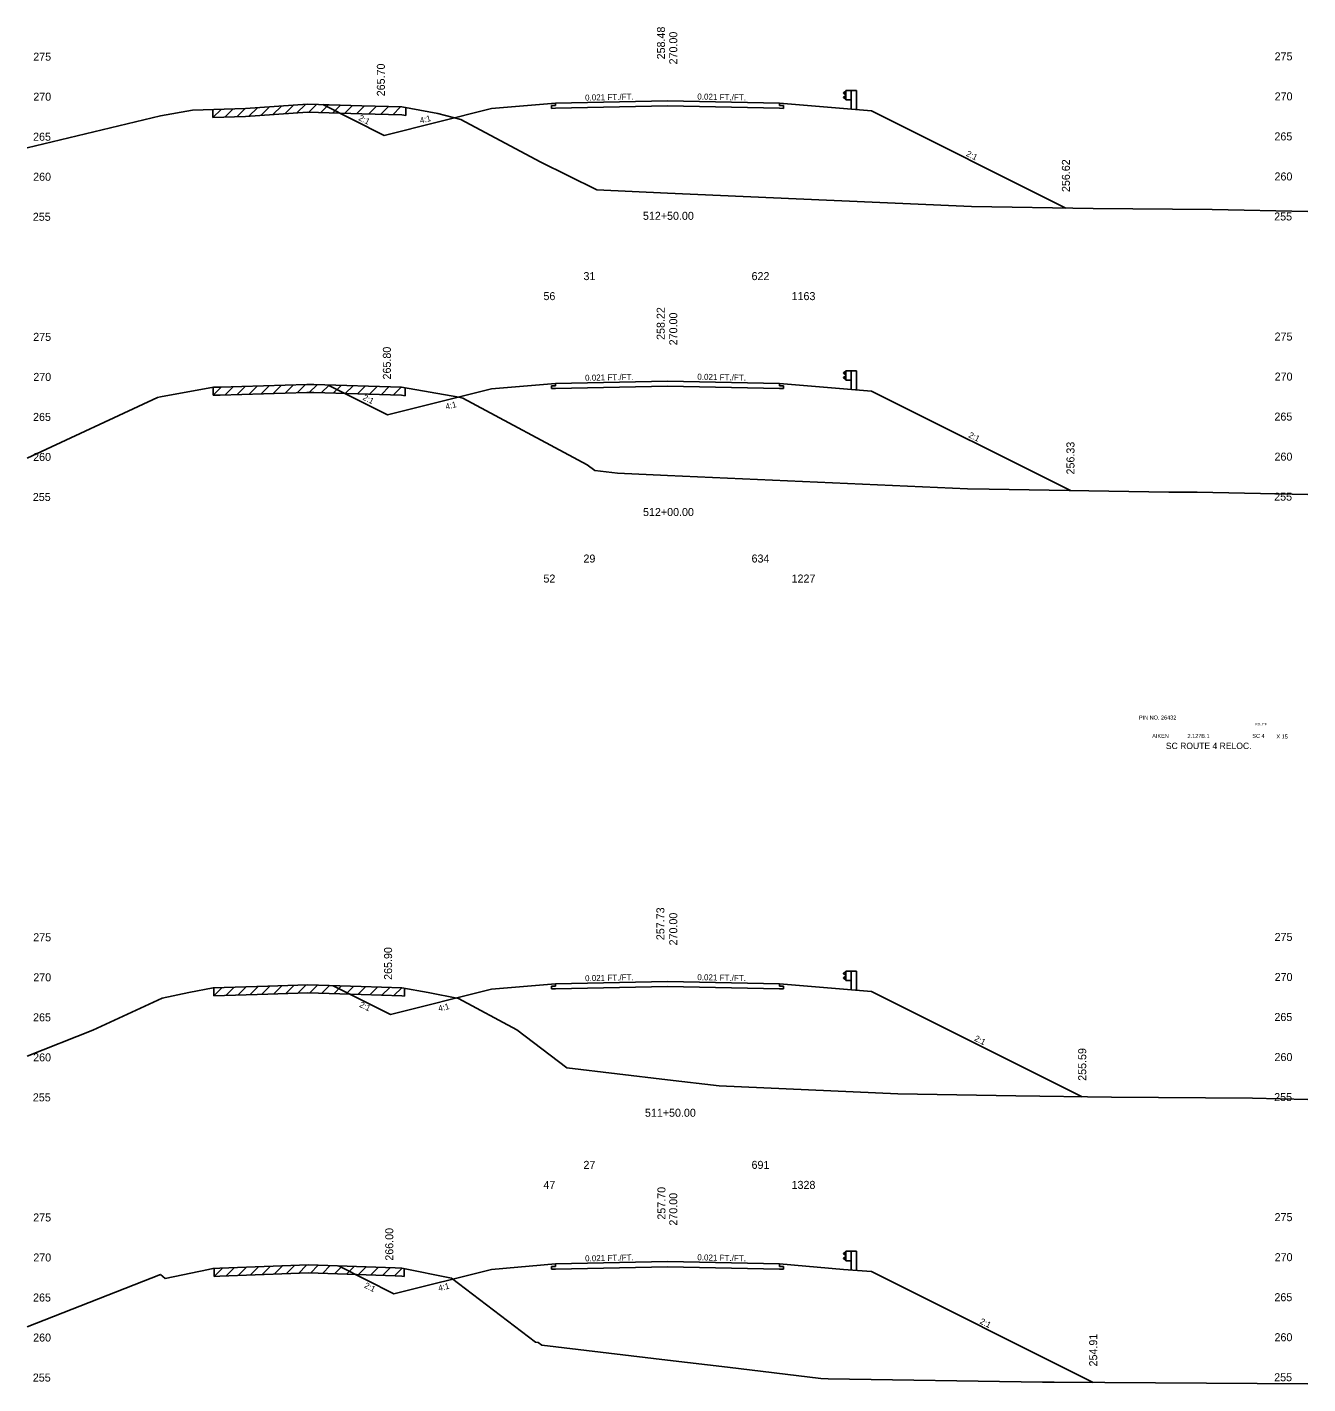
# Model space of a CAD drawing. Extents: x 2967 to 4323, y -3677 to -817.
# Drawn here: x 3188.8 to 3348.8, y -2050.1 to -1880.6 of the extents above; entities that cross this region are included whole.
import ezdxf

# ---------------------------------------------------------------- set-up
doc = ezdxf.new("R2010")
doc.units = 0
for name, color, linetype in [('Level 1', 7, 'Continuous'), ('Level 10', 7, 'Continuous'), ('Level 11', 7, 'Continuous'), ('Level 12', 7, 'Continuous'), ('Level 20', 7, 'Continuous'), ('Level 24', 7, 'Continuous'), ('Level 3', 7, 'Continuous'), ('Level 32', 7, 'Continuous'), ('Level 33', 7, 'Continuous'), ('Level 59', 7, 'Continuous'), ('Level 6', 7, 'Continuous'), ('Level 60', 7, 'Continuous'), ('Level 61', 7, 'Continuous'), ('Level 7', 7, 'Continuous')]:
    doc.layers.add(name, color=color, linetype=linetype)

msp = doc.modelspace()

# ---------------------------------------------------------------- linework, layer by layer
at = {"layer": 'Level 11'}
for p, q in [((3254.76, -1890.43), (3254.26, -1890.44)), ((3254.26, -1890.44), (3254.26, -1890.78)), ((3254.26, -1890.78), (3254.76, -1890.77)), ((3254.76, -1890.13), (3254.76, -1890.43)), ((3282.76, -1890.43), (3282.76, -1890.13)), ((3283.26, -1890.44), (3282.76, -1890.43)), ((3282.76, -1890.77), (3283.26, -1890.78)), ((3283.26, -1890.78), (3283.26, -1890.44)), ((3254.76, -1925.13), (3254.76, -1925.43)), ((3282.76, -1925.43), (3282.76, -1925.13)), ((3254.76, -1925.43), (3254.26, -1925.44)), ((3254.26, -1925.44), (3254.26, -1925.78)), ((3254.26, -1925.78), (3254.76, -1925.77)), ((3283.26, -1925.44), (3282.76, -1925.43)), ((3282.76, -1925.77), (3283.26, -1925.78)), ((3283.26, -1925.78), (3283.26, -1925.44)), ((3254.76, -2000.43), (3254.26, -2000.44)), ((3254.26, -2000.44), (3254.26, -2000.78)), ((3254.26, -2000.78), (3254.76, -2000.77)), ((3254.76, -2000.13), (3254.76, -2000.43)), ((3282.76, -2000.43), (3282.76, -2000.13)), ((3283.26, -2000.44), (3282.76, -2000.43)), ((3282.76, -2000.77), (3283.26, -2000.78)), ((3283.26, -2000.78), (3283.26, -2000.44)), ((3254.76, -2035.13), (3254.76, -2035.43)), ((3282.76, -2035.43), (3282.76, -2035.13)), ((3254.76, -2035.43), (3254.26, -2035.44)), ((3254.26, -2035.44), (3254.26, -2035.78)), ((3254.26, -2035.78), (3254.76, -2035.77)), ((3283.26, -2035.44), (3282.76, -2035.43)), ((3282.76, -2035.77), (3283.26, -2035.78)), ((3283.26, -2035.78), (3283.26, -2035.44))]:
    msp.add_line(p, q, dxfattribs=at)
at = {"layer": 'Level 12'}
for p, q in [((3268.76, -1890.48), (3254.76, -1890.77)), ((3282.76, -1890.77), (3268.76, -1890.48)), ((3268.76, -1925.48), (3254.76, -1925.77)), ((3282.76, -1925.77), (3268.76, -1925.48)), ((3268.76, -2000.48), (3254.76, -2000.77)), ((3282.76, -2000.77), (3268.76, -2000.48)), ((3268.76, -2035.48), (3254.76, -2035.77)), ((3282.76, -2035.77), (3268.76, -2035.48))]:
    msp.add_line(p, q, dxfattribs=at)
at = {"layer": 'Level 24'}
for p, q in [((3291.03, -1888.62), (3290.76, -1888.82)), ((3290.76, -1888.82), (3290.76, -1888.87)), ((3290.76, -1888.87), (3291.03, -1889.07)), ((3290.76, -1889.39), (3291.03, -1889.19)), ((3290.76, -1889.44), (3290.76, -1889.39)), ((3291.03, -1889.64), (3290.76, -1889.44)), ((3291.03, -1889.72), (3291.03, -1888.55)), ((3291.03, -1888.55), (3291.7, -1888.55)), ((3291.7, -1888.55), (3291.7, -1890.88)), ((3291.7, -1888.55), (3292.36, -1888.55)), ((3292.36, -1888.55), (3292.36, -1890.93)), ((3291.03, -1889.72), (3291.7, -1889.72)), ((3291.03, -1923.62), (3290.76, -1923.82)), ((3290.76, -1923.82), (3290.76, -1923.87)), ((3290.76, -1923.87), (3291.03, -1924.07)), ((3290.76, -1924.39), (3291.03, -1924.19)), ((3290.76, -1924.44), (3290.76, -1924.39)), ((3291.03, -1924.64), (3290.76, -1924.44)), ((3291.03, -1924.72), (3291.03, -1923.55)), ((3291.03, -1923.55), (3291.7, -1923.55)), ((3291.03, -1924.72), (3291.7, -1924.72)), ((3291.7, -1923.55), (3291.7, -1925.88)), ((3291.7, -1923.55), (3292.36, -1923.55)), ((3292.36, -1923.55), (3292.36, -1925.93)), ((3291.03, -1998.62), (3290.76, -1998.82)), ((3290.76, -1998.82), (3290.76, -1998.87)), ((3290.76, -1998.87), (3291.03, -1999.07)), ((3290.76, -1999.39), (3291.03, -1999.19)), ((3290.76, -1999.44), (3290.76, -1999.39)), ((3291.03, -1999.64), (3290.76, -1999.44)), ((3291.03, -1999.72), (3291.03, -1998.55)), ((3291.03, -1998.55), (3291.7, -1998.55)), ((3291.03, -1999.72), (3291.7, -1999.72)), ((3291.7, -1998.55), (3291.7, -2000.88)), ((3291.7, -1998.55), (3292.36, -1998.55)), ((3292.36, -1998.55), (3292.36, -2000.93)), ((3291.03, -2033.62), (3290.76, -2033.82)), ((3291.03, -2034.72), (3291.03, -2033.55)), ((3291.03, -2033.55), (3291.7, -2033.55)), ((3291.7, -2033.55), (3291.7, -2035.88)), ((3291.7, -2033.55), (3292.36, -2033.55)), ((3292.36, -2033.55), (3292.36, -2035.93)), ((3290.76, -2033.82), (3290.76, -2033.87)), ((3290.76, -2033.87), (3291.03, -2034.07)), ((3290.76, -2034.39), (3291.03, -2034.19)), ((3290.76, -2034.44), (3290.76, -2034.39)), ((3291.03, -2034.64), (3290.76, -2034.44)), ((3291.03, -2034.72), (3291.7, -2034.72))]:
    msp.add_line(p, q, dxfattribs=at)
at = {"layer": 'Level 59'}
for p, q in [((3254.76, -1890.13), (3268.76, -1889.84)), ((3268.76, -1889.84), (3282.76, -1890.13)), ((3254.76, -1925.13), (3268.76, -1924.84)), ((3268.76, -1924.84), (3282.76, -1925.13)), ((3254.76, -2000.13), (3268.76, -1999.84)), ((3268.76, -1999.84), (3282.76, -2000.13)), ((3254.76, -2035.13), (3268.76, -2034.84)), ((3268.76, -2034.84), (3282.76, -2035.13))]:
    msp.add_line(p, q, dxfattribs=at)
at = {"layer": 'Level 6'}
for p, q in [((3246.76, -1890.8), (3254.76, -1890.13)), ((3282.76, -1890.13), (3290.76, -1890.8)), ((3290.76, -1890.8), (3294.26, -1891.09)), ((3246.76, -1925.8), (3254.76, -1925.13)), ((3282.76, -1925.13), (3290.76, -1925.8)), ((3290.76, -1925.8), (3294.26, -1926.09)), ((3246.76, -2000.8), (3254.76, -2000.13)), ((3282.76, -2000.13), (3290.76, -2000.8)), ((3290.76, -2000.8), (3294.26, -2001.09)), ((3246.76, -2035.8), (3254.76, -2035.13)), ((3282.76, -2035.13), (3290.76, -2035.8)), ((3290.76, -2035.8), (3294.26, -2036.09))]:
    msp.add_line(p, q, dxfattribs=at)
at = {"layer": 'Level 60'}
for p, q in [((3205.43, -1891.73), (3209.42, -1891)), ((3209.42, -1891), (3216.02, -1890.8)), ((3216.02, -1890.8), (3223.78, -1890.26)), ((3223.78, -1890.26), (3230.56, -1890.45)), ((3230.56, -1890.45), (3235.59, -1890.6)), ((3235.59, -1890.6), (3240.06, -1891.4)), ((3188.76, -1895.69), (3205.43, -1891.73)), ((3240.06, -1891.4), (3242.95, -1892.17)), ((3242.95, -1892.17), (3252.84, -1897.46)), ((3252.84, -1897.46), (3259.94, -1900.97)), ((3259.94, -1900.97), (3268.76, -1901.36)), ((3268.76, -1901.36), (3288.61, -1902.23)), ((3288.61, -1902.23), (3306.72, -1903.04)), ((3306.72, -1903.04), (3321.92, -1903.28)), ((3321.92, -1903.28), (3336.81, -1903.4)), ((3336.81, -1903.4), (3348.76, -1903.64)), ((3188.76, -1934.47), (3205.05, -1926.89)), ((3205.05, -1926.89), (3205.44, -1926.81)), ((3205.44, -1926.81), (3212.04, -1925.62)), ((3212.04, -1925.62), (3212.88, -1925.59)), ((3212.88, -1925.59), (3223.72, -1925.26)), ((3223.72, -1925.26), (3224.56, -1925.29)), ((3224.56, -1925.29), (3235.54, -1925.59)), ((3235.54, -1925.59), (3242.69, -1926.87)), ((3242.69, -1926.87), (3243.21, -1926.97)), ((3243.21, -1926.97), (3258.73, -1935.3)), ((3258.73, -1935.3), (3259.66, -1936.01)), ((3259.66, -1936.01), (3262.5, -1936.34)), ((3262.5, -1936.34), (3268.76, -1936.62)), ((3268.76, -1936.62), (3306.24, -1938.3)), ((3306.24, -1938.3), (3308.95, -1938.34)), ((3308.95, -1938.34), (3331.37, -1938.72)), ((3331.37, -1938.72), (3334.91, -1938.74)), ((3334.91, -1938.74), (3348.76, -1939.03)), ((3205.63, -2001.91), (3208.97, -2001.2)), ((3208.97, -2001.2), (3212.01, -2000.65)), ((3212.01, -2000.65), (3218.82, -2000.41)), ((3218.82, -2000.41), (3223.82, -2000.26)), ((3223.82, -2000.26), (3230.5, -2000.48)), ((3230.5, -2000.48), (3235.57, -2000.62)), ((3235.57, -2000.62), (3238.87, -2001.21)), ((3238.87, -2001.21), (3242.66, -2001.98)), ((3196.96, -2005.94), (3205.63, -2001.91)), ((3242.66, -2001.98), (3249.93, -2005.88)), ((3188.76, -2009.19), (3196.96, -2005.94)), ((3249.93, -2005.88), (3256.2, -2010.63)), ((3256.2, -2010.63), (3268.76, -2012.11)), ((3268.76, -2012.11), (3275.22, -2012.88)), ((3275.22, -2012.88), (3297.55, -2013.88)), ((3297.55, -2013.88), (3312.27, -2014.11)), ((3312.27, -2014.11), (3324.21, -2014.31)), ((3324.21, -2014.31), (3341.83, -2014.42)), ((3341.83, -2014.42), (3348.76, -2014.57)), ((3212.84, -2035.65), (3223.9, -2035.25)), ((3223.9, -2035.25), (3234.75, -2035.62)), ((3188.76, -2043), (3205.41, -2036.43)), ((3205.41, -2036.43), (3206, -2036.95)), ((3206, -2036.95), (3211.43, -2035.8)), ((3211.43, -2035.8), (3211.96, -2035.68)), ((3211.96, -2035.68), (3212.84, -2035.65)), ((3234.75, -2035.62), (3235.59, -2035.66)), ((3235.59, -2035.66), (3241.78, -2036.91)), ((3241.78, -2036.91), (3252.28, -2044.88)), ((3252.28, -2044.88), (3252.59, -2044.94)), ((3252.59, -2044.94), (3253.08, -2045.28)), ((3253.08, -2045.28), (3268.76, -2047.14)), ((3268.76, -2047.14), (3276.25, -2048.03)), ((3276.25, -2048.03), (3287.93, -2049.42)), ((3287.93, -2049.42), (3288.85, -2049.46)), ((3288.85, -2049.46), (3315.6, -2049.88)), ((3315.6, -2049.88), (3317.05, -2049.9)), ((3317.05, -2049.9), (3348.74, -2050.11)), ((3348.74, -2050.11), (3348.76, -2050.11))]:
    msp.add_line(p, q, dxfattribs=at)
at = {"layer": 'Level 61'}
for p, q in [((3212.98, -1890.9), (3211.95, -1891.93)), ((3211.95, -1890.93), (3211.95, -1891.93)), ((3214.48, -1890.85), (3213.45, -1891.88)), ((3215.98, -1890.81), (3214.95, -1891.84)), ((3216.02, -1891.8), (3223.78, -1891.26)), ((3217.53, -1890.7), (3216.45, -1891.77)), ((3219.03, -1890.59), (3217.95, -1891.67)), ((3220.53, -1890.49), (3219.45, -1891.56)), ((3222.03, -1890.38), (3220.95, -1891.46)), ((3223.53, -1890.28), (3222.45, -1891.35)), ((3223.78, -1891.26), (3230.56, -1891.45)), ((3224.92, -1890.29), (3223.95, -1891.27)), ((3226.42, -1890.33), (3225.45, -1891.31)), ((3227.92, -1890.37), (3226.95, -1891.35)), ((3229.42, -1890.41), (3228.45, -1891.39)), ((3230.92, -1890.46), (3229.95, -1891.43)), ((3232.42, -1890.5), (3231.45, -1891.47)), ((3233.92, -1890.55), (3232.95, -1891.52)), ((3235.42, -1890.6), (3234.45, -1891.57)), ((3236.05, -1891.68), (3236.05, -1890.68)), ((3211.95, -1891.93), (3216.02, -1891.8)), ((3230.56, -1891.45), (3235.59, -1891.6)), ((3235.59, -1891.6), (3236.05, -1891.68)), ((3213.05, -1925.58), (3212.01, -1926.62)), ((3212.01, -1925.62), (3212.01, -1926.62)), ((3212.01, -1926.62), (3212.04, -1926.62)), ((3212.04, -1926.62), (3212.88, -1926.59)), ((3212.88, -1926.59), (3223.72, -1926.26)), ((3214.55, -1925.54), (3213.51, -1926.57)), ((3216.05, -1925.49), (3215.01, -1926.52)), ((3217.55, -1925.45), (3216.51, -1926.48)), ((3219.05, -1925.4), (3218.01, -1926.43)), ((3220.55, -1925.36), (3219.51, -1926.39)), ((3222.05, -1925.31), (3221.01, -1926.34)), ((3223.55, -1925.27), (3222.51, -1926.3)), ((3223.72, -1926.26), (3224.56, -1926.29)), ((3224.98, -1925.3), (3224.01, -1926.27)), ((3224.56, -1926.29), (3235.54, -1926.59)), ((3226.49, -1925.34), (3225.51, -1926.32)), ((3227.99, -1925.38), (3227.01, -1926.36)), ((3229.49, -1925.42), (3228.51, -1926.4)), ((3230.99, -1925.46), (3230.01, -1926.44)), ((3232.49, -1925.5), (3231.51, -1926.48)), ((3233.99, -1925.54), (3233.01, -1926.52)), ((3235.49, -1925.59), (3234.51, -1926.56)), ((3235.54, -1926.59), (3235.98, -1926.67)), ((3235.98, -1926.67), (3235.98, -1925.67)), ((3213.12, -2000.61), (3212.08, -2001.65)), ((3212.08, -2000.65), (3212.08, -2001.65)), ((3212.08, -2001.65), (3218.82, -2001.41)), ((3214.62, -2000.56), (3213.58, -2001.6)), ((3216.12, -2000.5), (3215.08, -2001.54)), ((3217.62, -2000.45), (3216.58, -2001.49)), ((3219.11, -2000.4), (3218.08, -2001.43)), ((3218.82, -2001.41), (3223.82, -2001.26)), ((3220.61, -2000.35), (3219.58, -2001.38)), ((3222.11, -2000.31), (3221.08, -2001.34)), ((3223.61, -2000.26), (3222.58, -2001.29)), ((3223.82, -2001.26), (3230.5, -2001.48)), ((3225.05, -2000.3), (3224.08, -2001.26)), ((3226.55, -2000.35), (3225.58, -2001.32)), ((3228.05, -2000.4), (3227.08, -2001.37)), ((3229.55, -2000.45), (3228.58, -2001.42)), ((3231.05, -2000.5), (3230.08, -2001.47)), ((3230.5, -2001.48), (3235.57, -2001.62)), ((3232.55, -2000.54), (3231.58, -2001.51)), ((3234.05, -2000.58), (3233.08, -2001.55)), ((3235.55, -2000.62), (3234.58, -2001.6)), ((3235.91, -2001.68), (3235.91, -2000.68)), ((3235.57, -2001.62), (3235.91, -2001.68)), ((3220.68, -2035.37), (3219.64, -2036.4)), ((3222.18, -2035.31), (3221.14, -2036.35)), ((3223.68, -2035.26), (3222.64, -2036.3)), ((3225.11, -2035.29), (3224.14, -2036.26)), ((3226.61, -2035.34), (3225.64, -2036.31)), ((3213.18, -2035.64), (3212.14, -2036.68)), ((3212.14, -2035.68), (3212.14, -2036.68)), ((3212.14, -2036.68), (3212.84, -2036.65)), ((3212.84, -2036.65), (3223.9, -2036.25)), ((3214.68, -2035.58), (3213.64, -2036.62)), ((3216.18, -2035.53), (3215.14, -2036.57)), ((3217.68, -2035.47), (3216.64, -2036.51)), ((3219.18, -2035.42), (3218.14, -2036.46)), ((3223.9, -2036.25), (3234.75, -2036.62)), ((3228.11, -2035.39), (3227.14, -2036.36)), ((3229.61, -2035.45), (3228.64, -2036.41)), ((3231.11, -2035.5), (3230.14, -2036.46)), ((3232.61, -2035.55), (3231.64, -2036.52)), ((3234.11, -2035.6), (3233.14, -2036.57)), ((3235.6, -2035.66), (3234.64, -2036.62)), ((3234.75, -2036.62), (3235.59, -2036.66)), ((3235.59, -2036.66), (3235.84, -2036.71)), ((3235.84, -2036.71), (3235.84, -2035.71))]:
    msp.add_line(p, q, dxfattribs=at)
at = {"layer": 'Level 7'}
for p, q in [((3225.71, -1890.31), (3233.37, -1894.15)), ((3246.76, -1890.8), (3233.37, -1894.15)), ((3294.26, -1891.09), (3318.53, -1903.23)), ((3226.36, -1925.34), (3233.77, -1929.05)), ((3246.76, -1925.8), (3233.77, -1929.05)), ((3294.26, -1926.09), (3319.1, -1938.51)), ((3227.01, -2000.37), (3234.17, -2003.95)), ((3246.76, -2000.8), (3234.17, -2003.95)), ((3294.26, -2001.09), (3320.57, -2014.25)), ((3227.64, -2035.38), (3234.57, -2038.85)), ((3246.76, -2035.8), (3234.57, -2038.85)), ((3294.26, -2036.09), (3321.94, -2049.93))]:
    msp.add_line(p, q, dxfattribs=at)

# ---------------------------------------------------------------- texts
at = {"layer": 'Level 1'}
for s, p in [('31', (3258.26, -1912.23)), ('622', (3279.26, -1912.23)), ('56', (3253.26, -1914.73)), ('1163', (3284.26, -1914.73)), ('29', (3258.26, -1947.51)), ('634', (3279.26, -1947.51)), ('52', (3253.26, -1950.01)), ('1227', (3284.26, -1950.01)), ('27', (3258.26, -2023.25)), ('691', (3279.26, -2023.25)), ('47', (3253.26, -2025.75)), ('1328', (3284.26, -2025.75))]:
    msp.add_text(s, height=1, dxfattribs=at).set_placement(p)
at = {"layer": 'Level 10'}
for s, p in [('258.48', (3268.45, -1884.66)), ('258.22', (3268.41, -1919.7)), ('257.73', (3268.37, -1994.68)), ('257.70', (3268.5, -2029.59))]:
    msp.add_text(s, height=1, rotation=90, dxfattribs=at).set_placement(p)
for s, p in [('512+50.00', (3265.69, -1904.7)), ('512+00.00', (3265.7, -1941.7)), ('511+50.00', (3265.94, -2016.74))]:
    msp.add_text(s, height=1, dxfattribs=at).set_placement(p)
at = {"layer": 'Level 20'}
for s, height, p in [('PIN NO. 26432', 0.5, (3327.65, -1967.12)), ('ROUTE', 0.3, (3342.19, -1967.86)), ('AIKEN', 0.5, (3329.31, -1969.42)), (' 2.127B.1', 0.5, (3333.53, -1969.42)), ('SC 4', 0.5, (3341.82, -1969.42)), ('X 15', 0.5, (3344.83, -1969.49)), ('SC ROUTE 4 RELOC.', 0.8, (3331.02, -1970.81))]:
    msp.add_text(s, height=height, dxfattribs=at).set_placement(p)
at = {"layer": 'Level 3'}
for s, p in [(' 275', (3189.15, -1884.82)), (' 275', (3344.23, -1884.78)), (' 270', (3189.16, -1889.82)), (' 270', (3344.24, -1889.78)), (' 265', (3189.13, -1894.82)), (' 265', (3344.21, -1894.78)), (' 260', (3189.14, -1899.82)), (' 260', (3344.22, -1899.78)), (' 255', (3189.1, -1904.82)), (' 255', (3344.18, -1904.78)), (' 275', (3189.15, -1919.82)), (' 275', (3344.23, -1919.78)), (' 270', (3189.16, -1924.82)), (' 270', (3344.24, -1924.78)), (' 265', (3189.13, -1929.82)), (' 265', (3344.21, -1929.78)), (' 260', (3189.14, -1934.82)), (' 260', (3344.22, -1934.78)), (' 255', (3344.18, -1939.78)), (' 255', (3189.1, -1939.82)), (' 275', (3189.15, -1994.82)), (' 275', (3344.23, -1994.78)), (' 270', (3189.16, -1999.82)), (' 270', (3344.24, -1999.78)), (' 265', (3189.13, -2004.82)), (' 265', (3344.21, -2004.78)), (' 260', (3189.14, -2009.82)), (' 260', (3344.22, -2009.78)), (' 255', (3189.1, -2014.82)), (' 255', (3344.18, -2014.78)), (' 275', (3189.15, -2029.82)), (' 275', (3344.23, -2029.78)), (' 270', (3189.16, -2034.82)), (' 270', (3344.24, -2034.78)), (' 265', (3344.21, -2039.78)), (' 265', (3189.13, -2039.82)), (' 260', (3189.14, -2044.82)), (' 260', (3344.22, -2044.78)), (' 255', (3189.1, -2049.82)), (' 255', (3344.18, -2049.78))]:
    msp.add_text(s, height=1, dxfattribs=at).set_placement(p)
at = {"layer": 'Level 32'}
for s, rotation, p in [('0.021 FT./FT.', 1.1916, (3258.47, -1889.81)), ('0.021 FT./FT.', 358.8084, (3272.48, -1889.67)), ('2:1', 333.435, (3230.09, -1892.21)), ('4:1', 14.0362, (3237.91, -1892.68)), ('2:1', 333.435, (3306, -1896.68)), ('0.021 FT./FT.', 1.1916, (3258.47, -1924.81)), ('0.021 FT./FT.', 358.8084, (3272.48, -1924.67)), ('2:1', 333.435, (3230.61, -1927.13)), ('4:1', 14.0362, (3241.11, -1928.42)), ('2:1', 333.435, (3306.29, -1931.83)), ('0.021 FT./FT.', 1.1916, (3258.47, -1999.81)), ('0.021 FT./FT.', 358.8084, (3272.48, -1999.67)), ('2:1', 333.435, (3230.19, -2002.97)), ('4:1', 14.0362, (3240.22, -2003.6)), ('2:1', 333.435, (3307.02, -2007.19)), ('0.021 FT./FT.', 1.1916, (3258.47, -2034.81)), ('0.021 FT./FT.', 358.8084, (3272.48, -2034.67)), ('2:1', 333.435, (3230.8, -2038.05)), ('4:1', 14.0362, (3240.22, -2038.53)), ('2:1', 333.435, (3307.7, -2042.53))]:
    msp.add_text(s, height=0.75, rotation=rotation, dxfattribs=at).set_placement(p)
at = {"layer": 'Level 33'}
for s, p in [('265.70', (3233.45, -1889.27)), ('256.62', (3319.03, -1901.23)), ('265.80', (3234.2, -1924.64)), ('256.33', (3319.6, -1936.51)), ('265.90', (3234.35, -1999.64)), ('255.59', (3321.07, -2012.25)), ('266.00', (3234.5, -2034.72)), ('254.91', (3322.44, -2047.93))]:
    msp.add_text(s, height=1, rotation=90, dxfattribs=at).set_placement(p)
at = {"layer": 'Level 59'}
for p in [(3269.98, -1885.66), (3269.98, -1920.75), (3269.98, -1995.71), (3269.98, -2030.71)]:
    msp.add_text(' 270.00', height=1, rotation=90, dxfattribs=at).set_placement(p)

doc.saveas('drawing.dxf')
